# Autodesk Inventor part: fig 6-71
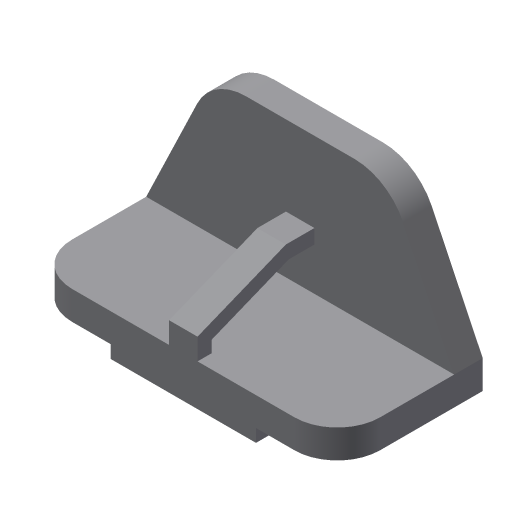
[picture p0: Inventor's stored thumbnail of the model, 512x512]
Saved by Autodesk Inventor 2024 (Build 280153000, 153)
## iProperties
Shininess: 77.0
Length Units: 11269
Angle Units: 11279
Time Units: 11290
Mass Units: 11283
Length Display Precision: 3
Angle Display Precision: 2
Created: 2001-12
Part Number: fig 6-71
Document SubType Name: Modeling
Designer: Renu Muthoo
Density: 1 g/cm^3
Material: Generic
Appearance: Default
Density: 0.0
Volumn: 0.0
Area: 0.0
PropertySet Name: Model Information
Control State: 0
Master: False
Checked Out: False
Author: Renu Muthoo
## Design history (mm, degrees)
sketch "Sketch2"
  geometry: L1 (-67.219, 19.116)-(148.781, 19.116); L2 (148.781, 19.116)-(148.781, -0.884); L3 (-67.219, -0.884)-(-67.219, 19.116); L4 (-10.219, -0.884)-(-10.219, -9.884); L5 (-10.219, -9.884)-(91.781, -9.884); L6 (91.781, -9.884)-(91.781, -0.884); L7 (148.781, -0.884)-(91.781, -0.884); L8 (-10.219, -0.884)-(-67.219, -0.884)
  constraints: 16 end point, 5 parallel, 4 perpendicular, 2 equal length, 1 horizontal
  dimensions: "d0" = 102 distance of L4.end L5.end; "d1" = 57 distance of L4.start L3.start; "d2" = 29 distance between parallel lines of L1 L5; "d3" = 20 distance of L1.end L2.end
extrude "Extrusion1" new body sketch "Sketch2" distance "d4" = 102; taper "d5" = 0 deg
sketch "Sketch3"
  geometry: L1 (67.219, -19.116)-(-148.781, -19.116) reference; L2 (67.219, -19.116)-(31.475, -93.564); L3 (-2.781, -115.116)-(-78.781, -115.116); L4 (-113.038, -93.564)-(-148.781, -19.116); A1 r 38 centre (-2.781, -77.116) between (-2.781, -115.116) and (31.475, -93.564); A2 r 38 centre (-78.781, -77.116) between (-113.038, -93.564) and (-78.781, -115.116)
  constraints: 6 end point, 4 point on circle, 4 tangent, 2 centre point, 1 equal length, 1 equal radius, 1 parallel
  dimensions: "d6" = 96 distance between parallel lines of L3 L1; "d7" = 38 radius of A1; "d8" = 76 distance of A2.centre A1.centre
extrude "Extrusion2" join sketch "Sketch3" distance "d9" = 20; taper "d10" = 0 deg
fillet "Fillet1" dims "d11" = 30
workplane "Work Plane1"
sketch "Sketch7"
  geometry: L1 (0, -82)-(-15, -82); L2 (-15, -82)-(-40, -20); L3 (-40, -20)-(-40, 0); L4 (0, -82)-(20, -82) reference; L5 (0, 0)-(-74.447, 0) reference
  constraints: 6 end point, 2 point on line, 1 horizontal, 1 perpendicular
  dimensions: "d32" = 20 distance of L2.end L3.end; "d33" = 15 distance of L1.start L1.end; "d34" = 40 distance of L5.start L3.end
feature "Rib4" sketch "Sketch7" dims "d55" = 10, "d56" = 20, "d57" = 0
body "Solid1"
other parameters: "d12" = -108
